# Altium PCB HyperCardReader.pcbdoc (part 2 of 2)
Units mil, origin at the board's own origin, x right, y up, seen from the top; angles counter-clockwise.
Board outline 2181.35 x 1859.05 mil, 2 copper layers (Top Layer, Bottom Layer); 44 components, 43 nets, 186 pads, 102 vias.
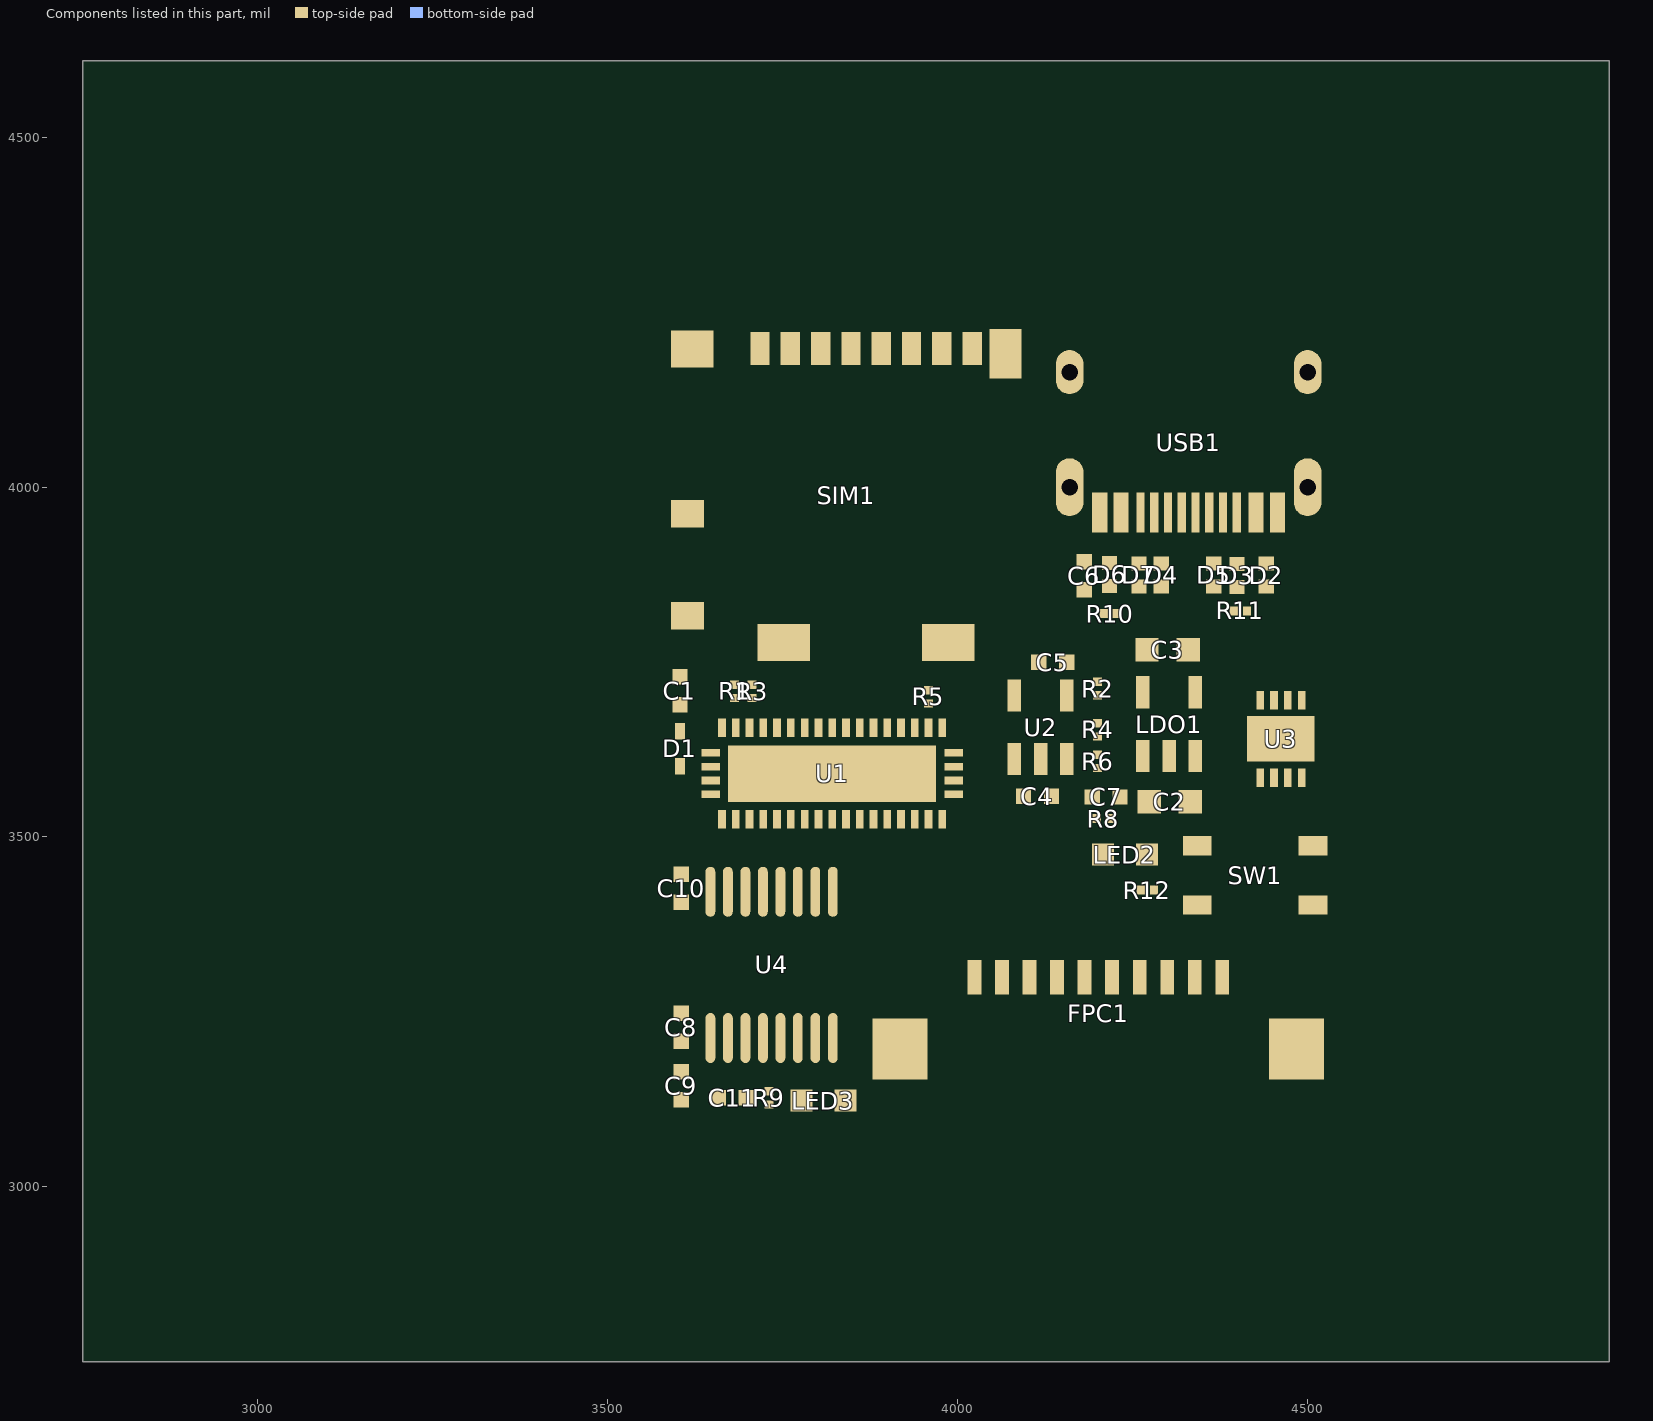
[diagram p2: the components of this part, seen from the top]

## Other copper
Top Layer:
  region net VCC-CARD: 3616.69,3707.95 3627.06,3697.1 ccw(c3668.22,3655.94) 3614.35,3677.99 3592.83,3699.99 ccw(c3592.83,3739.77)
  region net VCC-CARD: 3610.85,3655.49 3595.85,3655.49 ccw(c3521.78,3655.49) 3592.35,3677.99 3614.35,3677.99 ccw(c3684.92,3655.49)
  region net VBUS-USB: 4232.36,3547 4232.36,3567 ccw(c4257.09,4710.45) 4257.09,3566.73 4257.09,3533.27 ccw(c4232.36,3517.86)
  region net VBUS-USB: 4254.95,3596.73 4274.95,3596.73 ccw(c4312.45,3596.73) 4289.95,3566.73 4257.09,3566.73 ccw(c4045.69,3566.73)
  region net VCC-3V3-LDO: 4274.95,3720.8 4254.95,3720.8 ccw(c3730.97,3720.8) 4254.09,3750.8 4287.56,3750.8 ccw(c4316.95,3720.8)
  region net VCC-3V3-LDO: 4224.09,3742 4224.09,3762 ccw(c4224.09,3799.5) 4254.09,3777 4254.09,3750.8 ccw(c4254.09,3695.29)
  region net VCC-READ: 4101.86,3540.99 4086.86,3540.99 ccw(c4079.46,3540.99) 4083.36,3547.28 4105.36,3547.28 ccw(c4109.25,3540.99)
  region net VCC-READ: 4076.07,3565.96 4086.68,3576.57 ccw(c4105.36,3596.87) 4105.36,3569.28 4083.36,3547.28 ccw(c4055.77,3547.28)
  region net VBUS-USB: 4105.75,3728.07 4095.14,3738.68 ccw(c4070.08,3763.74) 4105.36,3760.28 4127.36,3738.28 ccw(c4130.81,3703)
  region net VBUS-USB: 4190.58,3909.31 4197.65,3902.24 ccw(c4218.87,3886.33) 4192.35,3886.33 4174.67,3904.01 ccw(c4174.67,3930.52)
  region net VBUS-USB: 4266.82,3567 4266.82,3547 ccw(c4266.82,3271.15) 4243.36,3546 4243.36,3568 ccw(c4266.82,3842.85)
  region net VBUS-USB: 4222.85,3594 4247.85,3594 ccw(c4320.8,3568) 4243.36,3568 4221.36,3568 ccw(c3996.02,3594)
  region net VDD-3V3: 3615.35,3166.99 3595.35,3166.99 ccw(c3144.85,3166.99) 3594.35,3196.99 3616.35,3196.99 ccw(c4065.85,3166.99)
  region net VDD-3V3: 3642.37,3217.99 3642.37,3197.99 ccw(c3642.37,2859.11) 3616.35,3196.99 3616.35,3218.99 ccw(c3642.37,3556.88)
  region net VDD-3V3: 3595.35,3205.01 3615.35,3205.01 ccw(c4065.85,3205.01) 3616.35,3175.01 3594.35,3175.01 ccw(c3144.85,3205.01)
  region net VCC-3V3-CARD: 3629.17,3438.78 3619.02,3427.72 ccw(c3595.15,3395.9) 3595.15,3435.68 3616.25,3457.68 ccw(c3673.05,3482.66)
  region net VCC-3V3-CARD: 3595.85,3480.18 3610.85,3480.18 ccw(c3660.43,3480.18) 3616.25,3457.68 3594.25,3457.68 ccw(c3436.85,3480.18)
  region net VCC-READ: 3667.58,3143.3 3674.65,3136.23 ccw(c3695.86,3120.32) 3669.35,3120.32 3651.67,3138 ccw(c3651.67,3164.52)
  region net CPUX-RX: 4425.2,3899.47 4433.17,3905.65 ccw(c4449.08,3926.86) 4449.08,3900.34 4430.51,3883.56 ccw(c4403.99,3883.56)
  region net CC1: 4415.02,3884.57 4416.97,3874.14 ccw(c4353.95,3811.12) 4410.28,3880.18 4410.28,3892.57 ccw(c4428.27,3897.82)
  region net CC1: 4385.42,3899.91 4390.56,3903.25 ccw(c4400.1,3915.98) 4400.1,3900.07 4388.6,3890.36 ccw(c4372.69,3890.36)
  region net USB0-DP: 4306.93,3885.66 4309.29,3874.82 ccw(c4281.17,3846.7) 4302.19,3880.46 4302.19,3893.66 ccw(c4320.18,3898.91)
  region net USB0-DP: 4288.35,3909.34 4294.35,3909.34 ccw(c4305.6,3909.34) 4298.85,3900.34 4283.85,3900.34 ccw(c4277.1,3909.34)
  region net USB0-DM: 4356.88,3909.34 4362.88,3909.34 ccw(c4374.13,3909.34) 4367.38,3900.34 4355.51,3900.34 ccw(c4326.69,3909.34)
  region net CC2: 4231.37,3881.62 4226.23,3878.27 ccw(c4216.69,3865.55) 4216.69,3881.46 4228.19,3891.16 ccw(c4244.1,3891.16)
  region net CC2: 4226.23,3904.53 4231.37,3901.18 ccw(c4244.1,3891.64) 4228.19,3891.64 4216.69,3901.34 ccw(c4216.69,3917.25)
  region net CPUX-TX: 4256.35,3906 4262.35,3906 ccw(c4268.15,3906) 4266.85,3900.34 4251.85,3900.34 ccw(c4250.55,3906)
  region net SDC-TF-D2: 4060.55,3332.79 4066.55,3332.79 ccw(c4077.8,3332.79) 4071.05,3323.79 4056.05,3323.79 ccw(c4049.3,3332.79)
  region net SDC-TF-D3: 4099.9,3332.79 4105.9,3332.79 ccw(c4117.15,3332.79) 4110.4,3323.79 4095.4,3323.79 ccw(c4088.65,3332.79)
  region net SDC-TF-CMD: 4139.3,3329.05 4145.3,3329.05 ccw(c4150.62,3329.05) 4149.8,3323.79 4134.8,3323.79 ccw(c4133.97,3329.05)
  region net VCC-CARD: 4190.65,3248.3 4172.65,3248.3 ccw(c3762.18,3248.29) 4171.8,3274.58 4191.49,3274.58 ccw(c4601.11,3248.29)
  region net SDC-TF-CLK: 4207.97,3326.14 4215.62,3326.98 ccw(c4225.16,3339.7) 4225.16,3323.79 4211.15,3316.59 ccw(c4195.24,3316.59)
  region net SDC-TF-D0: 4284.74,3331.36 4296.06,3328.53 ccw(c4309.31,3341.78) 4304.06,3323.79 4289.9,3323.79 ccw(c4267.35,3313.96)
  region net SDC-TF-D1: 4326.12,3322.99 4330.62,3326.98 ccw(c4340.16,3339.7) 4340.16,3323.79 4329.3,3313.44 ccw(c4313.39,3313.44)
  region net VBUS-USB: 4272.94,3643.66 4279.9,3636.48 ccw(c4301.11,3620.57) 4274.6,3620.57 4257.03,3638.36 ccw(c4257.03,3664.87)
  region net VBUS-USB: 4324.8,3640.48 4334.62,3644.8 ccw(c4350.21,3660.39) 4349.4,3638.36 4330.1,3624.57 ccw(c4303.59,3624.57)
  region net $1N4433: 4193.84,3505.35 4203.84,3505.35 ccw(c4222.59,3505.35) 4211.34,3490.35 4192.1,3490.35 ccw(c4128.32,3505.35)
  region net VCC-3V3-LDO: 4275.85,3454.5 4265.85,3454.5 ccw(c4258.35,3450.59) 4258.35,3459.05 4283.35,3459.05 ccw(c4283.35,3450.59)
  region net $1N4375: 3746.22,3112.49 3746.22,3122.49 ccw(c3746.22,3141.24) 3761.22,3129.99 3761.22,3107.16 ccw(c3746.22,3088.72)
  region net VDD-3V3: 3818.92,3131.36 3820.26,3144.16 ccw(c3836.17,3165.38) 3836.17,3138.86 3824.22,3115.45 ccw(c3797.7,3115.45)
  region net SEL: 3674.48,3684.55 3667,3691.21 ccw(c3644.35,3713.86) 3674.97,3704.46 3687.73,3692.52 ccw(c3697.13,3661.9)
  region net READ-VCC-EN: 4213.84,3726.51 4213.84,3716.51 ccw(c4213.84,3689.87) 4206.73,3715.54 4206.73,3727.48 ccw(c4213.84,3753.15)
  region net READ-VCC-EN: 4178.97,3716.51 4178.97,3726.51 ccw(c4178.97,3843.33) 4193.97,3727.48 4193.97,3715.54 ccw(c4178.97,3599.69)
  region net VCC-3V3-LDO: 3727.73,3722.51 3727.73,3712.51 ccw(c3727.73,3595.69) 3712.73,3711.54 3712.73,3723.48 ccw(c3727.73,3839.33)
  region net SEL1: 3702.25,3684.83 3695.18,3691.9 ccw(c3681.13,3704.46) 3699.97,3704.46 3712.73,3692.52 ccw(c3732.61,3654.46)
  region net $1N1961: 4203.35,3628.52 4197.35,3628.52 ccw(c4183.67,3628.52) 4193.97,3637.52 4206.73,3637.52 ccw(c4217.03,3628.52)
  region net VCC-3V3-LDO: 3962.81,3721.05 3969.89,3713.97 ccw(c3982.72,3701.14) 3964.73,3703.54 3951.97,3715.48 ccw(c3948.73,3735.13)
  region net EN: 3963.74,3669.52 3953.74,3669.52 ccw(c3889.05,3669.52) 3951.97,3684.52 3964.73,3684.52 ccw(c4077.55,3669.52)
  region net $1N1961: 4197.35,3632.48 4203.35,3632.48 ccw(c4217.03,3632.48) 4206.73,3623.48 4193.97,3623.48 ccw(c4183.67,3632.48)
  region net $1N1961: 4184.97,3614.51 4184.97,3620.51 ccw(c4184.97,3635.64) 4193.97,3623.48 4193.97,3611.54 ccw(c4184.97,3599.38)
  region net SEL1-LED: 4233.35,3531 4233.35,3521 ccw(c4233.35,3487.41) 4223.83,3519.62 4223.83,3532.38 ccw(c4233.35,3564.59)
  region net $1N4433: 4203.84,3504.62 4193.84,3504.62 ccw(c4077.02,3504.62) 4192.87,3519.62 4204.81,3519.62 ccw(c4320.66,3504.62)
  region net LED-READ: 3718.31,3141.47 3725.39,3148.55 ccw(c3741.07,3164.23) 3736.73,3142.48 3723.97,3130.54 ccw(c3703.95,3127.11)
  region net $1N4375: 3751.73,3122.49 3751.73,3112.49 ccw(c3751.73,2995.67) 3736.73,3111.52 3736.73,3123.46 ccw(c3751.73,3239.31)
  region net CC2: 4233.18,3828.56 4237.01,3823.91 ccw(c4249.74,3814.36) 4233.83,3814.36 4223.63,3825.38 ccw(c4223.63,3841.29)
  region net CC1: 4419.18,3832.56 4423.01,3827.91 ccw(c4435.74,3818.36) 4419.83,3818.36 4409.63,3829.38 ccw(c4409.63,3845.29)
  region net SEL-BTN: 4286.18,3433.56 4290.01,3428.91 ccw(c4302.74,3419.36) 4286.83,3419.36 4276.63,3430.38 ccw(c4276.63,3446.29)
  region net VCC-3V3-LDO: 4240.87,3419 4240.87,3429 ccw(c4240.87,3511.33) 4255.87,3430.38 4255.87,3417.62 ccw(c4240.87,3336.67)
  region net VCC-3V3-LDO: 4256.35,3445 4266.35,3445 ccw(c4340.45,3445) 4267.81,3430.38 4255.87,3430.38 ccw(c4032,3445)
  region net SDC-CARD-D1: 4023.98,4165.51 4017.98,4165.51 ccw(c4006.73,4165.51) 4013.48,4174.51 4028.48,4174.51 ccw(c4035.23,4165.51)
  region net SDC-CARD-D0: 3980.67,4165.51 3974.67,4165.51 ccw(c3963.42,4165.51) 3970.17,4174.51 3985.17,4174.51 ccw(c3991.92,4165.51)
  region net SDC-CARD-CLK: 3896.35,4165.51 3890.35,4165.51 ccw(c3879.1,4165.51) 3885.85,4174.51 3900.85,4174.51 ccw(c3907.6,4165.51)
  region net VCC-CARD: 3855.25,4152.01 3840.25,4152.01 ccw(c3796.8,4152.01) 3833.97,4174.51 3861.52,4174.51 ccw(c3898.69,4152.01)
  region net SDC-CARD-CMD: 3807.44,4165.51 3801.44,4165.51 ccw(c3790.19,4165.51) 3796.94,4174.51 3811.94,4174.51 ccw(c3818.69,4165.51)
  region net SDC-CARD-D3: 3764.14,4165.51 3758.14,4165.51 ccw(c3746.89,4165.51) 3753.64,4174.51 3768.64,4174.51 ccw(c3775.39,4165.51)
  region net SDC-CARD-D2: 3720.83,4167.52 3714.83,4167.52 ccw(c3707.15,4167.52) 3710.33,4174.51 3725.33,4174.51 ccw(c3728.5,4167.52)
  region net SEL-BTN: 4329.91,3468.81 4318.17,3465.55 ccw(c4304.92,3478.8) 4322.9,3473.54 4337.9,3473.54 ccw(c4343.16,3455.56)
  region net SEL-BTN: 4369.67,3492.32 4369.67,3482.32 ccw(c4370.95,3474.82) 4363.34,3474.82 4363.34,3499.82 ccw(c4370.95,3499.82)
  region net SEL-BTN: 4482.06,3506.22 4496.02,3506.4 ccw(c4511.93,3527.62) 4511.93,3501.1 4487.36,3490.31 ccw(c4460.84,3490.31)
  region net VCC-3V3-LDO: 3973.42,3683.83 3983.42,3683.83 ccw(c4203.4,3683.83) 3983.93,3668.83 3972.91,3668.83 ccw(c3753.44,3683.83)
  region net EN: 3953.74,3683.83 3963.74,3683.83 ccw(c4183.72,3683.83) 3964.25,3668.83 3953.22,3668.83 ccw(c3733.75,3683.83)
  region net SDC-CARD-D1: 3877,3676.65 3883,3676.65 ccw(c3896.41,3676.65) 3885.51,3668.83 3874.48,3668.83 ccw(c3863.58,3676.65)
  region net SDC-CARD-D0: 3857.31,3677.83 3863.31,3677.83 ccw(c3880.69,3677.83) 3865.82,3668.83 3854.8,3668.83 ccw(c3839.93,3677.83)
  region net SDC-CARD-CLK: 3837.63,3677.83 3843.63,3677.83 ccw(c3861,3677.83) 3846.14,3668.83 3835.11,3668.83 ccw(c3820.25,3677.83)
  region net SDC-CARD-CMD: 3798.26,3676.91 3804.26,3676.91 ccw(c3818.5,3676.91) 3806.77,3668.83 3795.74,3668.83 ccw(c3784.01,3676.91)
  region net SDC-CARD-D3: 3778.57,3677.83 3784.57,3677.83 ccw(c3801.95,3677.83) 3787.08,3668.83 3776.06,3668.83 ccw(c3761.19,3677.83)
  region net SDC-CARD-D2: 3758.89,3677.83 3764.89,3677.83 ccw(c3782.26,3677.83) 3767.4,3668.83 3756.37,3668.83 ccw(c3741.51,3677.83)
  region net SEL1: 3678.15,3672.8 3688.15,3672.8 ccw(c3703.77,3672.8) 3688.66,3668.83 3677.63,3668.83 ccw(c3662.52,3672.8)
  region net SEL: 3658.46,3680.6 3668.46,3680.6 ccw(c3804.04,3680.6) 3668.97,3668.83 3657.95,3668.83 ccw(c3522.88,3680.6)
  region net SDC-READ-D2: 3686.15,3503.14 3680.15,3503.14 ccw(c3662.77,3503.14) 3677.63,3512.14 3688.66,3512.14 ccw(c3703.52,3503.14)
  region net SDC-READ-D3: 3705.83,3503.14 3699.83,3503.14 ccw(c3682.45,3503.14) 3697.32,3512.14 3708.34,3512.14 ccw(c3723.21,3503.14)
  region net SDC-READ-CMD: 3724.85,3503.14 3718.85,3503.14 ccw(c3696,3503.14) 3717,3512.14 3728.03,3512.14 ccw(c3739.19,3503.14)
  region net SDC-READ-CLK: 3745.2,3503.14 3739.2,3503.14 ccw(c3721.82,3503.14) 3736.69,3512.14 3747.71,3512.14 ccw(c3762.58,3503.14)
  region net SDC-READ-D0: 3764.89,3503.14 3758.89,3503.14 ccw(c3741.51,3503.14) 3756.37,3512.14 3767.4,3512.14 ccw(c3782.26,3503.14)
  region net SDC-READ-D1: 3784.57,3503.14 3778.57,3503.14 ccw(c3761.19,3503.14) 3776.06,3512.14 3787.08,3512.14 ccw(c3801.95,3503.14)
  region net SDC-TF-D2: 3863.31,3503.14 3857.31,3503.14 ccw(c3839.93,3503.14) 3854.8,3512.14 3865.82,3512.14 ccw(c3880.69,3503.14)
  region net SDC-TF-D3: 3883,3503.14 3877,3503.14 ccw(c3859.62,3503.14) 3874.48,3512.14 3885.51,3512.14 ccw(c3900.37,3503.14)
  region net SDC-TF-CMD: 3902.68,3503.14 3896.68,3503.14 ccw(c3879.3,3503.14) 3894.17,3512.14 3905.19,3512.14 ccw(c3920.06,3503.14)
  region net SDC-TF-CLK: 3922.37,3503.14 3916.37,3503.14 ccw(c3898.99,3503.14) 3913.85,3512.14 3924.88,3512.14 ccw(c3939.74,3503.14)
  region net SDC-TF-D0: 3942.05,3503.14 3936.05,3503.14 ccw(c3918.67,3503.14) 3933.54,3512.14 3944.56,3512.14 ccw(c3959.43,3503.14)
  region net SDC-TF-D1: 3961.74,3507.61 3955.74,3507.61 ccw(c3950.41,3507.61) 3953.22,3512.14 3964.25,3512.14 ccw(c3967.06,3507.61)
  region net VCC-READ: 4088.87,3571.27 4073.87,3571.27 ccw(c4004.88,3571.27) 4071.73,3588.34 4091.02,3588.34 ccw(c4157.87,3571.27)
  region net $1N1961: 4174.82,3620.51 4174.82,3614.51 ccw(c4174.82,3603.26) 4165.82,3610.01 4165.82,3625.01 ccw(c4174.82,3631.76)
  region net READ-VCC-EN: 4172.19,3725.05 4173.71,3712.42 ccw(c4195.79,3690.34) 4165.82,3699.1 4165.82,3724.1 ccw(c4168.37,3728.87)
  region net VBUS-USB: 4092.55,3736.08 4098.97,3721.29 ccw(c4130.79,3697.43) 4091.02,3697.43 4071.73,3725.08 ccw(c4064.32,3764.3)
  region net SEL1-LED: 4412.31,3581 4412.31,3591 ccw(c4412.31,3611.18) 4427.31,3597.68 4427.31,3573.5 ccw(c4412.31,3562.25)
  region net VCC-3V3-LDO: 4457.51,3567.16 4447.51,3567.16 ccw(c4428.86,3567.16) 4447,3571.5 4458.02,3571.5 ccw(c4476.16,3567.16)
  region net SEL-BTN: 4477.19,3563.84 4467.19,3563.84 ccw(c4409.64,3563.84) 4466.68,3571.5 4477.7,3571.5 ccw(c4534.74,3563.84)
  region net CPUX-RX: 4488.88,3717.5 4494.88,3717.5 ccw(c4512.26,3717.5) 4497.39,3708.5 4486.37,3708.5 ccw(c4471.5,3717.5)
  region net CPUX-TX: 4469.19,3717.5 4475.19,3717.5 ccw(c4492.57,3717.5) 4477.7,3708.5 4466.68,3708.5 ccw(c4451.81,3717.5)
  region net SEL: 4447.51,3710.84 4457.51,3710.84 ccw(c4463.11,3710.84) 4458.02,3708.5 4447,3708.5 ccw(c4441.91,3710.84)
  region net READ-VCC-EN: 4412.31,3690.41 4412.31,3700.41 ccw(c4412.31,3719.16) 4427.31,3707.91 4427.31,3682.91 ccw(c4412.31,3671.66)
  region net VDD-3V3: 3609.85,3197.99 3609.85,3217.99 3615.45,3218.02 3620.87,3218.23 3625.93,3218.79 3628.28,3219.25 3630.48,3219.87 3632.49,3220.66 3634.31,3221.66 3635.91,3222.87 3637.27,3224.32 3638.37,3226.04 3639.18,3228.04 3639.68,3230.35 3639.85,3232.99 3639.85,3183.76 3639.68,3186.39 3639.18,3188.67 3638.37,3190.64 3637.27,3192.31 3635.91,3193.7 3634.31,3194.85 3632.49,3195.78 3630.48,3196.5 3628.28,3197.05 3625.93,3197.44 3620.87,3197.88 3615.45,3198
  region net VDD-3V3: 3650.81,3262.07 3667.65,3257.7 3665.08,3255.41 3662.59,3253.58 3660.25,3252.02 3658.16,3250.52 3656.4,3248.89 3655.66,3247.96 3655.04,3246.93 3654.53,3245.76 3654.16,3244.43 3653.93,3242.92 3653.85,3241.2 3639.85,3241.2 3640.1,3244.1 3640.79,3246.96 3641.87,3249.77 3643.27,3252.49 3644.93,3255.1 3646.79,3257.58 3648.76,3259.91
  region net VCC-READ: 3676.85,3168.76 3666.85,3168.76 3666.76,3171.51 3666.54,3174.12 3665.85,3178.69 3664.85,3183.76 3678.85,3183.76 3677.85,3178.69 3677.16,3174.12 3676.94,3171.51
  region net LED-READ: 3726.85,3168.76 3716.85,3168.76 3716.76,3171.51 3716.54,3174.12 3715.85,3178.69 3714.85,3183.76 3728.85,3183.76 3727.85,3178.69 3727.16,3174.12 3726.94,3171.51
  region net VDD-3V3: 3751.85,3168.76 3741.85,3168.76 3741.76,3171.51 3741.54,3174.12 3740.85,3178.69 3739.85,3183.76 3753.85,3183.76 3752.85,3178.69 3752.16,3174.12 3751.94,3171.51
  region net USB0-DP: 3793.85,3248.5 3799.85,3248.5 3800.02,3247.18 3800.48,3245.96 3801.12,3244.85 3801.85,3243.86 3803.23,3242.25 3803.68,3241.66 3803.85,3241.2 3789.85,3241.2 3790.02,3241.66 3790.48,3242.25 3791.85,3243.86 3792.58,3244.85 3793.23,3245.96 3793.68,3247.18
  region net USB0-DM: 3819.73,3249.62 3831.56,3252.96 3830.73,3252.02 3829.99,3250.92 3829.35,3249.7 3828.84,3248.41 3828.48,3247.08 3828.3,3245.75 3828.31,3244.46 3828.55,3243.25 3814.85,3241.2 3814.96,3242.46 3815.27,3243.63 3815.75,3244.74 3816.37,3245.79 3817.94,3247.76
  region net SDC-READ-D2: 3668.85,3459.24 3674.85,3459.24 3675.02,3457.61 3675.48,3456.08 3676.12,3454.68 3676.85,3453.43 3678.23,3451.44 3678.68,3450.73 3678.85,3450.24 3664.85,3450.24 3665.02,3450.73 3665.48,3451.44 3666.85,3453.43 3667.58,3454.68 3668.23,3456.08 3668.68,3457.61
  region net SDC-READ-D3: 3693.85,3459.24 3699.85,3459.24 3700.02,3457.61 3700.48,3456.08 3701.12,3454.68 3701.85,3453.43 3703.23,3451.44 3703.68,3450.73 3703.85,3450.24 3689.85,3450.24 3690.02,3450.73 3690.48,3451.44 3691.85,3453.43 3692.58,3454.68 3693.23,3456.08 3693.68,3457.61
  region net SDC-READ-CMD: 3718.85,3459.24 3724.85,3459.24 3725.02,3457.61 3725.48,3456.08 3726.12,3454.68 3726.85,3453.43 3728.23,3451.44 3728.68,3450.73 3728.85,3450.24 3714.85,3450.24 3715.02,3450.73 3715.48,3451.44 3716.85,3453.43 3717.58,3454.68 3718.23,3456.08 3718.68,3457.61
  region net SDC-READ-CLK: 3743.85,3459.24 3749.85,3459.24 3750.02,3457.61 3750.48,3456.08 3751.12,3454.68 3751.85,3453.43 3753.23,3451.44 3753.68,3450.73 3753.85,3450.24 3739.85,3450.24 3740.02,3450.73 3740.48,3451.44 3741.85,3453.43 3742.58,3454.68 3743.23,3456.08 3743.68,3457.61
  region net SDC-READ-D0: 3768.85,3459.24 3774.85,3459.24 3775.02,3457.61 3775.48,3456.08 3776.12,3454.68 3776.85,3453.43 3778.23,3451.44 3778.68,3450.73 3778.85,3450.24 3764.85,3450.24 3765.02,3450.73 3765.48,3451.44 3766.85,3453.43 3767.58,3454.68 3768.23,3456.08 3768.68,3457.61
  region net SDC-READ-D1: 3793.85,3459.24 3799.85,3459.24 3800.02,3457.61 3800.48,3456.08 3801.12,3454.68 3801.85,3453.43 3803.23,3451.44 3803.68,3450.73 3803.85,3450.24 3789.85,3450.24 3790.02,3450.73 3790.48,3451.44 3791.85,3453.43 3792.58,3454.68 3793.23,3456.08 3793.68,3457.61
  region net VBUS-USB: 4419.31,3992.51 4434.31,3992.51 ccw(c4437.64,4013.52) 4437.64,3992.25 4415.98,3992.25 ccw(c4415.98,4013.52)
  region net CPUX-RX: 4404.25,3932.5 4394.25,3932.5 ccw(c4389.89,3932.5) 4393.34,3935.16 4405.16,3935.16 ccw(c4408.61,3932.5)
  region net CC1: 4382.56,3926.16 4376.56,3926.16 ccw(c4361.17,3926.16) 4373.65,3935.16 4385.47,3935.16 ccw(c4397.95,3926.16)
  region net USB0-DM: 4362.88,3929.66 4356.88,3929.66 ccw(c4350.22,3929.66) 4353.97,3935.16 4365.79,3935.16 ccw(c4369.54,3929.66)
  region net USB0-DM: 4323.51,3929.84 4317.51,3929.84 ccw(c4311.18,3929.84) 4314.6,3935.16 4326.42,3935.16 ccw(c4329.84,3929.84)
  region net USB0-DP: 4303.82,3926.16 4297.82,3926.16 ccw(c4282.43,3926.16) 4294.91,3935.16 4306.73,3935.16 ccw(c4319.21,3926.16)
  region net CPUX-TX: 4284.14,3927.79 4278.14,3927.79 ccw(c4267.34,3927.79) 4275.23,3935.16 4287.05,3935.16 ccw(c4294.94,3927.79)
  region net CPUX-TX: 4278.14,3995.79 4284.14,3995.79 ccw(c4287.75,3995.79) 4287.05,3992.25 4275.23,3992.25 ccw(c4274.53,3995.79)
  region net CC2: 4259.99,3929.8 4249.84,3928.14 ccw(c4218.93,3959.05) 4255.54,3935.16 4267.36,3935.16 ccw(c4280.73,3909.06)
  region net VBUS-USB: 4239.44,4007.69 4252.67,3999.72 ccw(c4284.49,3975.85) 4244.72,3975.85 4223.06,3992.25 ccw(c3966.71,4280.42)
  region net VCC-CARD: 3688.05,4099.09 3677.44,4109.7 3679.2,4111.32 3680.73,4112.81 3681.35,4113.61 3681.85,4114.49 3682.19,4115.49 3682.36,4116.67 3695.02,4104.01 3693.84,4103.84 3692.84,4103.5 3691.96,4103 3691.16,4102.38 3689.67,4100.85
  region net VCC-CARD: 3840.25,4166.7 3855.25,4166.11 3855.14,4163.73 3855.08,4161.61 3855.18,4160.62 3855.43,4159.65 3855.87,4158.68 3856.56,4157.71 3838.67,4158.3 3839.41,4159.22 3839.9,4160.16 3840.19,4161.14 3840.33,4162.15 3840.33,4164.31
  region net SEL1-LED: 4425.76,3591 4425.76,3581 4424.64,3580.91 4423.51,3580.66 4421.28,3579.77 4419.18,3578.5 4417.36,3577.05 4417.36,3594.95 4419.18,3593.5 4421.28,3592.23 4423.51,3591.34 4424.64,3591.09
  region net SEL1-LED: 4229.81,3522.46 4236.89,3529.54 4237.63,3528.92 4238.31,3528.59 4238.97,3528.49 4239.63,3528.54 4241.11,3528.85 4243.02,3528.99 4230.36,3516.33 4230.5,3518.24 4230.81,3519.72 4230.86,3520.38 4230.76,3521.04 4230.43,3521.72
  region net VCC-3V3-LDO: 4246.76,3429 4246.76,3419 4245.64,3418.91 4244.51,3418.66 4242.28,3417.77 4240.18,3416.5 4238.36,3415.05 4238.36,3432.95 4240.18,3431.5 4242.28,3430.23 4244.51,3429.34 4245.64,3429.09
  region net VCC-3V3-LDO: 4231.76,3762 4231.76,3742 4229.11,3741.91 4226.61,3741.69 4222.23,3741 4219.01,3740.31 4217.35,3739.99 4217.35,3764.01 4219.01,3763.69 4222.23,3763 4226.61,3762.31 4229.11,3762.09
  region net USB0-DM: 4337.35,3845.77 4343.35,3851.67 4343.5,3850.31 4343.93,3849.01 4344.61,3847.77 4345.48,3846.62 4346.51,3845.58 4347.65,3844.66 4348.88,3843.89 4350.15,3843.27 4334.01,3835.54 4334.88,3837.93 4335.99,3840.61 4336.95,3843.32 4337.24,3844.59
  region net USB0-DP: 4318.35,3851.74 4324.35,3847.77 4324.52,3842.88 4324.88,3839.54 4325.23,3836.2 4325.37,3831.31 4312.22,3843.33 4313.6,3843.64 4314.82,3844.25 4315.87,3845.12 4316.74,3846.21 4317.44,3847.46 4317.94,3848.83 4318.25,3850.27
  region net VCC-CARD: 4172.65,3264.63 4190.65,3264.19 4190.43,3262.2 4190.05,3259.79 4189.93,3257.48 4190.1,3256.53 4190.49,3255.78 4172.6,3256.22 4173.42,3257.29 4173.81,3258.23 4173.87,3259.12 4173.7,3260 4173.04,3261.98 4172.76,3263.19
  region net VCC-CARD: 3632.07,3702.12 3621.47,3712.72 3623.22,3714.35 3624.76,3715.84 3625.38,3716.63 3625.87,3717.51 3626.22,3718.52 3626.39,3719.69 3639.04,3707.04 3637.87,3706.87 3636.86,3706.52 3635.98,3706.03 3635.19,3705.41 3633.7,3703.87
  region net VCC-CARD: 3644.68,3735.93 3655.28,3725.33 3653.53,3723.7 3651.99,3722.21 3651.37,3721.42 3650.88,3720.54 3650.53,3719.53 3650.36,3718.36 3637.71,3731.01 3638.88,3731.18 3639.89,3731.52 3640.77,3732.02 3641.56,3732.64 3643.05,3734.18
  region net VCC-3V3-LDO: 3715.94,3712.51 3715.94,3722.51 3717.06,3722.6 3718.19,3722.85 3720.43,3723.74 3722.52,3725.01 3724.34,3726.46 3724.34,3708.56 3722.52,3710.01 3720.43,3711.28 3718.19,3712.17 3717.06,3712.42
  region net VCC-3V3-LDO: 3967.94,3712.51 3967.94,3722.51 3969.06,3722.6 3970.19,3722.85 3972.43,3723.74 3974.52,3725.01 3976.34,3726.46 3976.34,3708.56 3974.52,3710.01 3972.43,3711.28 3970.19,3712.17 3969.06,3712.42
  region net VCC-3V3-LDO: 3983.42,3697.51 3973.42,3703.17 3973.31,3709.14 3973.07,3712.11 3972.6,3715.05 3987.47,3705.91 3986.28,3705.43 3985.34,3704.71 3984.63,3703.8 3984.12,3702.73 3983.77,3701.53 3983.56,3700.23
  region net SEL: 3667,3684.14 3659.92,3677.06 3659.17,3677.7 3658.45,3678.07 3657.74,3678.23 3657.02,3678.25 3655.44,3678.08 3653.48,3678.02 3666.35,3690.46 3666.2,3688.52 3665.93,3686.98 3665.9,3686.28 3666.03,3685.59 3666.37,3684.89
  region net USB0-DM: 4389.35,3219.64 4383.35,3223.59 4383.19,3228.49 4382.83,3231.84 4382.48,3235.18 4382.34,3240.08 4395.48,3228.05 4394.1,3227.74 4392.88,3227.13 4391.83,3226.26 4390.95,3225.17 4390.26,3223.92 4389.76,3222.55 4389.45,3221.11
  region net USB0-DP: 4372.47,3233.12 4368.23,3228.88 4367.54,3229.29 4366.7,3229.39 4365.74,3229.26 4364.7,3228.99 4362.58,3228.32 4361.58,3228.08 4360.68,3228.01 4373.34,3240.67 4373.27,3239.77 4373.03,3238.77 4372.36,3236.65 4372.09,3235.62 4371.96,3234.65 4372.06,3233.81
  region net SEL: 4385.42,3715.14 4392.49,3708.07 4391.76,3707.21 4391.14,3706.24 4390.19,3704.02 4389.61,3701.65 4389.34,3699.33 4376.68,3711.99 4379,3712.26 4381.37,3712.84 4383.59,3713.79 4384.56,3714.41
  region net CPUX-RX: 4386.08,4003.52 4381.83,3999.27 4380.67,4000.24 4379.54,4000.84 4378.41,4001.15 4377.25,4001.23 4374.7,4001.08 4371.68,4001.01 4384.34,4013.67 4384.27,4010.65 4384.12,4008.11 4384.21,4006.94 4384.51,4005.81 4385.11,4004.68
  region net CPUX-RX: 4494.88,3764.03 4488.88,3769.12 4488.59,3772.2 4487.91,3775.62 4487.12,3779.03 4486.5,3782.08 4501.58,3772.43 4500.33,3771.95 4499.12,3771.22 4497.99,3770.28 4496.97,3769.18 4496.12,3767.97 4495.46,3766.68 4495.03,3765.35
  region net CPUX-TX: 4475.19,3764.75 4469.19,3760.66 4469.08,3762.11 4468.77,3763.54 4468.26,3764.91 4467.56,3766.15 4466.68,3767.24 4465.63,3768.12 4464.41,3768.74 4463.04,3769.06 4476.36,3780.86 4476.14,3776.08 4475.74,3772.81 4475.36,3769.54
  region net VBUS-USB: 4265.82,4025.91 4254.03,4035.33 4255.78,4036.99 4257.31,4038.57 4257.91,4039.41 4258.37,4040.33 4258.64,4041.36 4258.71,4042.54 4272.5,4031.13 4271.32,4030.85 4270.34,4030.44 4269.52,4029.9 4268.79,4029.25 4267.42,4027.7
  region net VBUS-USB: 4277.01,4059.91 4287.61,4049.3 4285.86,4047.68 4284.33,4046.19 4283.7,4045.39 4283.21,4044.51 4282.86,4043.51 4282.7,4042.33 4270.04,4054.99 4271.21,4055.16 4272.22,4055.5 4273.1,4056 4273.89,4056.62 4275.38,4058.15
  region net CPUX-TX: 4324.97,4013.49 4319.57,4019.49 4320.9,4019.64 4322.22,4020.07 4323.49,4020.74 4324.68,4021.6 4325.76,4022.62 4326.69,4023.77 4327.44,4024.99 4327.97,4026.24 4336.92,4010.74 4334.14,4011.46 4330.97,4012.37 4327.79,4013.16
  region net VCC-READ: 3676.85,3141.39 3666.85,3141.39 3666.76,3142.51 3666.51,3143.64 3665.62,3145.87 3664.35,3147.96 3662.9,3149.79 3680.8,3149.79 3679.35,3147.96 3678.08,3145.87 3677.19,3143.64 3676.94,3142.51
  region net VCC-READ: 3666.85,3174.21 3676.85,3174.21 3676.94,3173.09 3677.19,3171.95 3678.08,3169.72 3679.35,3167.63 3680.8,3165.8 3662.9,3165.8 3664.35,3167.63 3665.62,3169.72 3666.51,3171.95 3666.76,3173.09
  region net VCC-READ: 4092.44,3532.3 4103.05,3542.91 4104.67,3541.15 4106.16,3539.62 4106.96,3539 4107.84,3538.5 4108.84,3538.16 4110.02,3537.99 4097.36,3525.33 4097.19,3526.51 4096.85,3527.51 4096.35,3528.39 4095.73,3529.19 4094.2,3530.68
  region net VCC-3V3-LDO: 4395.81,3559.54 4402.89,3552.46 4402.22,3551.68 4401.78,3550.88 4401.52,3550.07 4401.39,3549.22 4401.34,3545.33 4388.68,3557.99 4392.57,3558.04 4393.42,3558.17 4394.23,3558.43 4395.03,3558.87
  region net SEL: 3668.46,3655.74 cw(c3724.54,3655.3) 3684.89,3694.95 3677.81,3702.03 cw(c3656.55,3723.29) 3657.89,3693.25 3650.81,3686.18 cw(c3594.05,3655.74) 3658.46,3655.74
  region net USB0-DM: 4354.34,3919.88 cw(c4353.25,3916.42) 4356.88,3916.42 4359.88,3929.66 4356.88,3936.9 cw(c4332.66,3941.56) 4350.1,3924.12
Bottom Layer:
  region net VCC-CARD: 3697.47,4133.26 3711.61,4119.12 3709.8,4117.19 3708.19,4115.25 3705.58,4111.67 3703.79,4108.9 3702.84,4107.51 3685.86,4124.49 3687.26,4125.44 3690.02,4127.23 3693.6,4129.84 3695.54,4131.45
  region net VCC-CARD: 3832.94,4140 3832.94,4160 3835.59,4160.09 3838.09,4160.31 3842.47,4161 3845.69,4161.69 3847.35,4162.01 3847.35,4137.99 3845.69,4138.31 3842.47,4139 3838.09,4139.69 3835.59,4139.91
  region net SEL1-LED: 4392.22,3582 4393.71,3592 4394.83,3592.08 4395.95,3592.31 4398.14,3593.12 4400.22,3594.27 4402.12,3595.59 4400.63,3577.75 4398.88,3579.31 4396.77,3580.67 4394.49,3581.63 4393.34,3581.9
  region net SEL1-LED: 4250.42,3532.14 4257.49,3525.07 4256.76,3524.21 4256.14,3523.24 4255.19,3521.02 4254.61,3518.65 4254.34,3516.33 4241.68,3528.99 4244,3529.26 4246.37,3529.84 4248.59,3530.79 4249.56,3531.41
  region net VCC-3V3-LDO: 4244.76,3434 4244.76,3414 4242.11,3413.91 4239.61,3413.69 4235.23,3413 4232.01,3412.31 4230.35,3411.99 4230.35,3436.01 4232.01,3435.69 4235.23,3435 4239.61,3434.31 4242.11,3434.09
  region net VCC-3V3-LDO: 4213.09,3427.12 4227.23,3441.26 4229.16,3439.45 4231.1,3437.84 4234.68,3435.23 4237.45,3433.44 4238.84,3432.49 4221.86,3415.51 4220.91,3416.9 4219.12,3419.67 4216.51,3423.25 4214.9,3425.19
  region net VCC-3V3-LDO: 4214.23,3734.74 4200.09,3748.88 4201.9,3750.81 4203.51,3752.75 4206.12,3756.33 4207.91,3759.1 4208.86,3760.49 4225.84,3743.51 4224.45,3742.56 4221.68,3740.77 4218.1,3738.16 4216.16,3736.55
  region net USB0-DM: 4344.35,3813.16 4338.35,3819.39 4338.22,3820.44 4337.87,3821.5 4336.73,3823.67 4335.4,3825.8 4334.36,3827.8 4351.13,3821.56 4348.64,3820.03 4347.5,3819.13 4346.47,3818.13 4345.6,3817.03 4344.93,3815.84 4344.5,3814.55
  region net USB0-DP: 4327.16,3822.43 4323.23,3817.88 4322.08,3818.83 4320.96,3819.41 4319.82,3819.69 4318.66,3819.76 4316.12,3819.54 4313.12,3819.37 4325.32,3832.48 4325.33,3829.45 4325.19,3826.97 4325.28,3825.83 4325.58,3824.72 4326.18,3823.6
  region net VCC-CARD: 4171.35,3262.41 4191.35,3262.41 4191.44,3259.76 4191.66,3257.26 4192.35,3252.88 4193.04,3249.66 4193.36,3248 4169.34,3248 4169.66,3249.66 4170.35,3252.88 4171.04,3257.26 4171.26,3259.76
  region net VCC-CARD: 3631.14,3701.64 3618.29,3717.08 3619.27,3717.76 3620.45,3718.16 3623.06,3718.59 3624.29,3718.81 3625.33,3719.18 3626.1,3719.8 3626.49,3720.76 3637.63,3707.04 3636.35,3706.99 3635.37,3706.68 3634.6,3706.16 3633.96,3705.46 3632.76,3703.67 3632.04,3702.67
  region net VCC-3V3-LDO: 3748.76,3722.51 3748.76,3712.51 3747.64,3712.42 3746.51,3712.17 3744.28,3711.28 3742.18,3710.01 3740.36,3708.56 3740.36,3726.46 3742.18,3725.01 3744.28,3723.74 3746.51,3722.85 3747.64,3722.6
  region net VCC-3V3-LDO: 3998.76,3727.51 3998.76,3707.51 3996.11,3707.42 3993.61,3707.2 3989.23,3706.51 3986.01,3705.82 3984.35,3705.5 3984.35,3729.52 3986.01,3729.2 3989.23,3728.51 3993.61,3727.82 3996.11,3727.6
  region net VCC-3V3-LDO: 3967.94,3712.51 3967.94,3722.51 3969.06,3722.6 3970.19,3722.85 3972.43,3723.74 3974.52,3725.01 3976.34,3726.46 3976.34,3708.56 3974.52,3710.01 3972.43,3711.28 3970.19,3712.17 3969.06,3712.42
  region net SEL: 3662.42,3705.14 3669.49,3698.07 3668.76,3697.21 3668.14,3696.24 3667.19,3694.02 3666.61,3691.65 3666.34,3689.33 3653.68,3701.99 3656,3702.26 3658.37,3702.84 3660.59,3703.79 3661.56,3704.41
  region net USB0-DM: 4382.23,3247.88 4386.47,3252.12 4387.2,3251.67 4388.16,3251.45 4390.5,3251.51 4392.96,3251.84 4395.02,3251.99 4382.36,3239.33 4382.51,3241.39 4382.84,3243.85 4382.9,3246.19 4382.68,3247.15
  region net USB0-DP: 4366.35,3260.36 4372.35,3256.41 4372.52,3251.51 4372.87,3248.16 4373.22,3244.82 4373.36,3239.92 4360.22,3251.95 4361.6,3252.26 4362.82,3252.87 4363.87,3253.74 4364.75,3254.83 4365.44,3256.08 4365.94,3257.45 4366.25,3258.89
  region net SEL: 4360.94,3695 4360.94,3705 4362.06,3705.09 4363.19,3705.34 4365.43,3706.23 4367.52,3707.5 4369.34,3708.95 4369.34,3691.05 4367.52,3692.5 4365.43,3693.77 4363.19,3694.66 4362.06,3694.91
  region net CPUX-RX: 4364.47,3999.88 4360.23,4004.12 4361.12,4005.21 4361.55,4006.19 4361.62,4007.12 4361.44,4008.06 4360.76,4010.18 4360.47,4011.46 4360.34,4012.96 4373.72,4001.07 4372.15,4001 4370.81,4001.12 4368.61,4001.49 4367.62,4001.54 4366.64,4001.36 4365.61,4000.84
  region net CPUX-RX: 4485.51,3797.6 4493.48,3798.11 4494.3,3797.49 4495.33,3797.01 4497.77,3796.33 4500.33,3795.83 4502.52,3795.26 4486.7,3786.89 4487.3,3789.78 4487.5,3792.63 4487.36,3793.99 4487,3795.29 4486.4,3796.49
  region net CPUX-TX: 4461.35,3795.14 4467.35,3795.14 4467.54,3794.31 4468.07,3793.48 4469.77,3791.86 4471.74,3790.35 4473.3,3789.01 4455.4,3789.01 4456.96,3790.35 4458.93,3791.86 4460.63,3793.48 4461.16,3794.31
  region net CPUX-TX: 4342.35,4006.06 4336.35,4006.1 4336.22,4007.61 4335.84,4008.83 4335.25,4009.84 4334.49,4010.73 4332.59,4012.41 4330.41,4014.51 4348.31,4014.47 4346.12,4012.38 4344.21,4010.69 4343.45,4009.81 4342.86,4008.79 4342.48,4007.57
  region net VCC-READ: 3688.26,3165.3 3688.26,3150.3 3685.87,3150.39 3683.73,3150.42 3682.73,3150.3 3681.76,3150.03 3680.8,3149.56 3679.86,3148.85 3679.86,3166.75 3680.8,3166.04 3681.76,3165.57 3682.73,3165.29 3683.73,3165.17 3685.87,3165.21
  region net VCC-READ: 4126.26,3519.7 4115.65,3509.09 4114.03,3510.85 4112.54,3512.38 4111.74,3513 4110.86,3513.5 4109.86,3513.84 4108.68,3514.01 4121.34,3526.67 4121.51,3525.49 4121.85,3524.49 4122.35,3523.61 4122.97,3522.81 4124.5,3521.32
  region net VCC-3V3-LDO: 4399.35,3531.59 4379.35,3531.59 4379.26,3534.24 4379.04,3536.74 4378.35,3541.12 4377.66,3544.34 4377.34,3546 4401.36,3546 4401.04,3544.34 4400.35,3541.12 4399.66,3536.74 4399.44,3534.24

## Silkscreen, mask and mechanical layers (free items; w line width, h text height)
Top Silkscreen Layer:
  region: 3956.63,3318 ccw(c3940.35,3318) 3924.07,3318 ccw(c3940.35,3318)
  lines w6: 4124.35,3474.64 4124.35,3457.49 ; 4140,3457.49 4124.35,3457.49 ; 4180.75,3474.85 4141.71,3474.85 4124.35,3457.49
  text "ON->BOARD /  OFF->CARD" at 3854.88,3353.1 h36.18
  text "SWITCH" at 4310.9,3333.32 h38.94
Bottom Silkscreen Layer:
  text "v1.2" at 4080.67,4151.03 h38.94 r90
